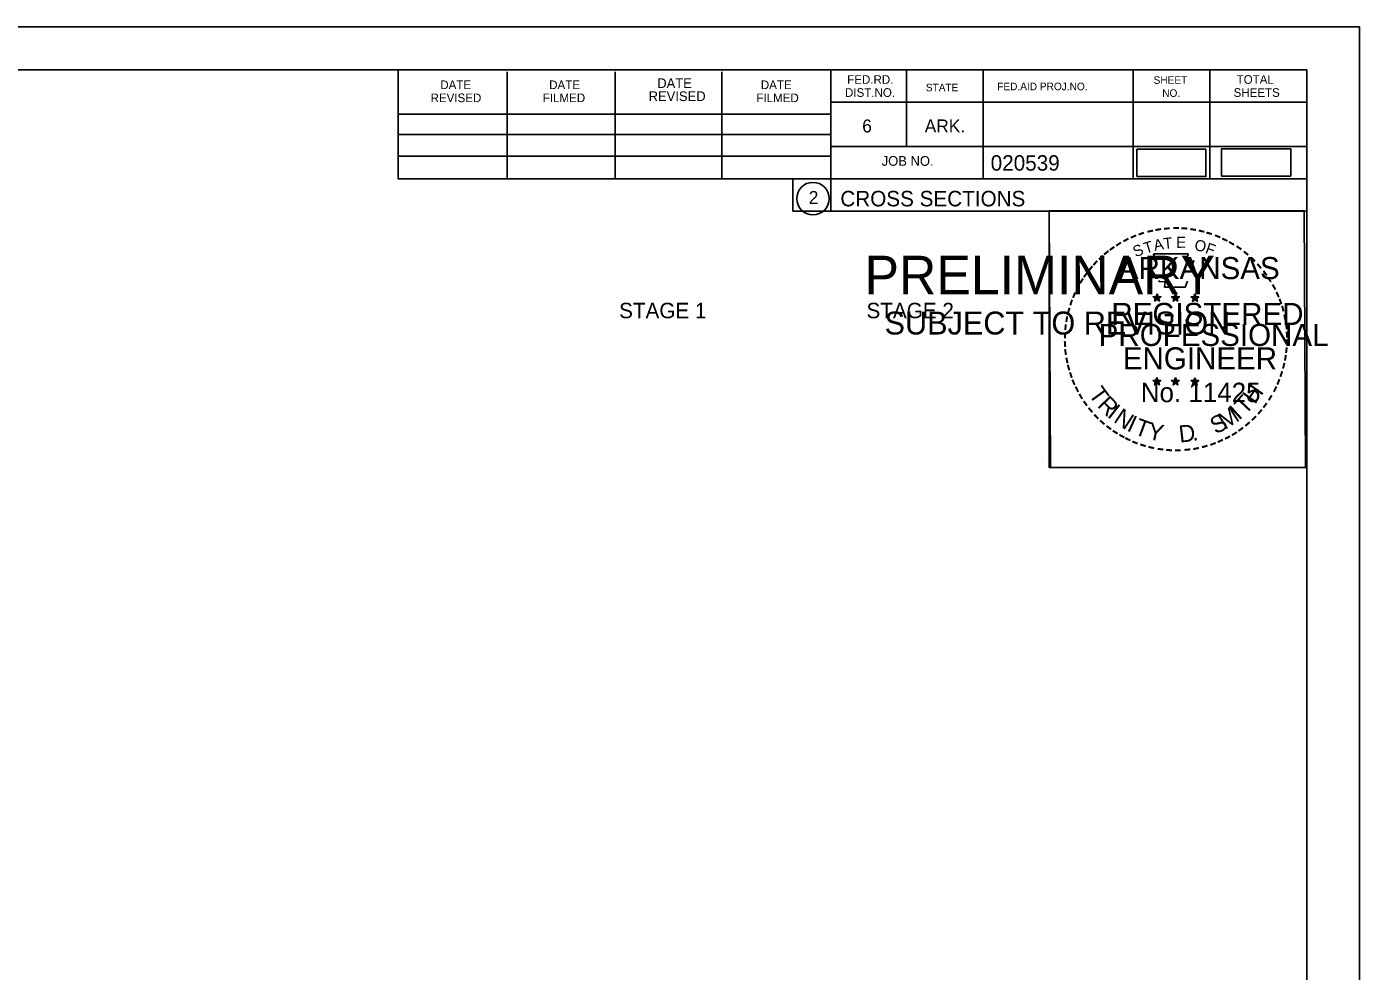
# Model space of a CAD drawing. Extents: x 915787 to 919910, y 133456 to 136717.
# Drawn here: x 916456.2 to 916576.9, y 134223.9 to 134309.4 of the extents above; entities that cross this region are included whole.
import ezdxf

# ---------------------------------------------------------------- set-up
doc = ezdxf.new("R2010")
doc.units = 0
for name, color, linetype in [('R_Border', 7, 'Continuous'), ('R_Border Notes', 7, 'Continuous'), ('R_Border PE', 7, 'Continuous'), ('R_Border Prem', 7, 'Continuous'), ('R_No Plot', 7, 'Continuous'), ('R_Xsect Slope', 7, 'Continuous')]:
    doc.layers.add(name, color=color, linetype=linetype)

msp = doc.modelspace()

# ---------------------------------------------------------------- linework, layer by layer
at = {"layer": 'R_Border'}
for p, q in [((916255.98, 134305.49), (916572.16, 134305.49)), ((916489.9, 134295.61), (916489.9, 134305.49)), ((916499.76, 134295.61), (916499.76, 134305.29)), ((916509.52, 134295.61), (916509.52, 134305.29)), ((916519.2, 134295.61), (916519.2, 134305.29)), ((916529.06, 134305.49), (916529.06, 134292.69)), ((916535.9, 134305.49), (916535.9, 134298.55)), ((916542.84, 134305.49), (916542.84, 134295.61)), ((916556.42, 134305.49), (916556.42, 134295.61)), ((916563.36, 134305.49), (916563.36, 134295.61)), ((916572.16, 134100.03), (916572.16, 134305.49)), ((916572.16, 134302.55), (916529.06, 134302.55)), ((916572.16, 134302.57), (916572.16, 134302.57)), ((916489.9, 134301.47), (916529.06, 134301.47)), ((916489.9, 134299.61), (916529.06, 134299.61)), ((916489.9, 134295.61), (916489.9, 134297.67)), ((916489.9, 134297.67), (916529.06, 134297.67)), ((916572.16, 134298.55), (916529.06, 134298.55)), ((916532.02, 134298.55), (916572.16, 134298.55)), ((916572.16, 134295.61), (916489.9, 134295.61)), ((916529.06, 134292.69), (916572.16, 134292.69))]:
    msp.add_line(p, q, dxfattribs=at)
msp.add_circle((916527.44, 134293.82), 1.47, dxfattribs=at)
at = {"layer": 'R_Border PE'}
for p, q in [((916558.24, 134284.94), (916558.59, 134284.83)), ((916558.24, 134284.94), (916558.49, 134284.9)), ((916558.24, 134284.94), (916558.48, 134284.82)), ((916558.37, 134284.54), (916558.59, 134284.83)), ((916558.37, 134284.54), (916558.5, 134284.78)), ((916558.37, 134284.54), (916558.59, 134284.75)), ((916558.59, 134285.2), (916558.55, 134284.95)), ((916558.59, 134284.83), (916558.59, 134285.2)), ((916558.59, 134285.2), (916558.64, 134284.95)), ((916558.94, 134284.94), (916558.59, 134284.83)), ((916558.8, 134284.54), (916558.59, 134284.83)), ((916558.8, 134284.54), (916558.59, 134284.75)), ((916558.94, 134284.94), (916558.65, 134284.89)), ((916558.8, 134284.54), (916558.66, 134284.83)), ((916558.94, 134284.94), (916558.73, 134284.84)), ((916559.91, 134284.94), (916560.26, 134284.83)), ((916559.91, 134284.94), (916560.16, 134284.9)), ((916559.91, 134284.94), (916560.15, 134284.82)), ((916560.04, 134284.54), (916560.26, 134284.83)), ((916560.04, 134284.54), (916560.17, 134284.78)), ((916560.04, 134284.54), (916560.26, 134284.75)), ((916560.26, 134285.2), (916560.22, 134284.95)), ((916560.26, 134284.83), (916560.26, 134285.2)), ((916560.26, 134285.2), (916560.31, 134284.95)), ((916560.61, 134284.94), (916560.26, 134284.83)), ((916560.47, 134284.54), (916560.26, 134284.83)), ((916560.47, 134284.54), (916560.26, 134284.75)), ((916560.61, 134284.94), (916560.32, 134284.89)), ((916560.47, 134284.54), (916560.33, 134284.83)), ((916560.61, 134284.94), (916560.4, 134284.84)), ((916561.67, 134284.93), (916562.02, 134284.82)), ((916561.67, 134284.93), (916561.93, 134284.89)), ((916561.67, 134284.93), (916561.91, 134284.81)), ((916561.81, 134284.52), (916562.02, 134284.82)), ((916561.81, 134284.52), (916561.93, 134284.77)), ((916561.81, 134284.52), (916562.02, 134284.74)), ((916562.02, 134285.19), (916561.98, 134284.93)), ((916562.02, 134284.82), (916562.02, 134285.19)), ((916562.02, 134285.19), (916562.07, 134284.94)), ((916562.37, 134284.93), (916562.02, 134284.82)), ((916562.24, 134284.52), (916562.02, 134284.82)), ((916562.24, 134284.52), (916562.02, 134284.74)), ((916562.37, 134284.93), (916562.08, 134284.88)), ((916562.24, 134284.52), (916562.1, 134284.81)), ((916562.37, 134284.93), (916562.17, 134284.83)), ((916558.24, 134277.37), (916558.58, 134277.26)), ((916558.24, 134277.37), (916558.49, 134277.33)), ((916558.24, 134277.37), (916558.47, 134277.25)), ((916558.37, 134276.96), (916558.58, 134277.26)), ((916558.37, 134276.96), (916558.49, 134277.21)), ((916558.37, 134276.96), (916558.58, 134277.18)), ((916558.58, 134277.62), (916558.54, 134277.37)), ((916558.58, 134277.26), (916558.58, 134277.62)), ((916558.58, 134277.62), (916558.63, 134277.37)), ((916558.93, 134277.37), (916558.58, 134277.26)), ((916558.8, 134276.96), (916558.58, 134277.26)), ((916558.8, 134276.96), (916558.58, 134277.18)), ((916558.93, 134277.37), (916558.65, 134277.32)), ((916558.8, 134276.96), (916558.66, 134277.25)), ((916558.93, 134277.37), (916558.73, 134277.27)), ((916559.9, 134277.37), (916560.25, 134277.26)), ((916559.9, 134277.37), (916560.16, 134277.33)), ((916559.9, 134277.37), (916560.14, 134277.25)), ((916560.04, 134276.96), (916560.25, 134277.26)), ((916560.04, 134276.96), (916560.16, 134277.21)), ((916560.04, 134276.96), (916560.25, 134277.18)), ((916560.25, 134277.62), (916560.21, 134277.37)), ((916560.25, 134277.26), (916560.25, 134277.62)), ((916560.25, 134277.62), (916560.3, 134277.37)), ((916560.6, 134277.37), (916560.25, 134277.26)), ((916560.47, 134276.96), (916560.25, 134277.26)), ((916560.47, 134276.96), (916560.25, 134277.18)), ((916560.6, 134277.37), (916560.31, 134277.32)), ((916560.47, 134276.96), (916560.33, 134277.25)), ((916560.6, 134277.37), (916560.4, 134277.27)), ((916561.67, 134277.36), (916562.02, 134277.25)), ((916561.67, 134277.36), (916561.92, 134277.32)), ((916561.67, 134277.36), (916561.91, 134277.24)), ((916561.8, 134276.95), (916562.02, 134277.25)), ((916561.8, 134276.95), (916561.93, 134277.2)), ((916561.8, 134276.95), (916562.02, 134277.17)), ((916562.02, 134277.61), (916561.98, 134277.36)), ((916562.02, 134277.25), (916562.02, 134277.61)), ((916562.02, 134277.61), (916562.07, 134277.36)), ((916562.37, 134277.36), (916562.02, 134277.25)), ((916562.23, 134276.95), (916562.02, 134277.25)), ((916562.23, 134276.95), (916562.02, 134277.17)), ((916562.37, 134277.36), (916562.08, 134277.31)), ((916562.23, 134276.95), (916562.1, 134277.24)), ((916562.37, 134277.36), (916562.16, 134277.26))]:
    msp.add_line(p, q, dxfattribs=at)
for points in [[(916558.28, 134288.82), (916558.55, 134287.99)], [(916561.79, 134287.9), (916561.93, 134288.18), (916561.25, 134288.16), (916561.4, 134288.82), (916558.28, 134288.82)], [(916558.77, 134286.4), (916558.77, 134286.31), (916559.34, 134286.29), (916559.28, 134285.82), (916561.15, 134285.82), (916561.35, 134286.36)], [(916558.59, 134285.2), (916558.8, 134284.54), (916558.24, 134284.94), (916558.94, 134284.94), (916558.37, 134284.54), (916558.59, 134285.2)], [(916560.26, 134285.2), (916560.47, 134284.54), (916559.91, 134284.94), (916560.61, 134284.94), (916560.04, 134284.54), (916560.26, 134285.2)], [(916562.02, 134285.19), (916562.24, 134284.52), (916561.67, 134284.93), (916562.37, 134284.93), (916561.81, 134284.52), (916562.02, 134285.19)], [(916558.58, 134277.62), (916558.8, 134276.96), (916558.24, 134277.37), (916558.93, 134277.37), (916558.37, 134276.96), (916558.58, 134277.62)], [(916560.25, 134277.62), (916560.47, 134276.96), (916559.9, 134277.37), (916560.6, 134277.37), (916560.04, 134276.96), (916560.25, 134277.62)], [(916562.02, 134277.61), (916562.23, 134276.95), (916561.67, 134277.36), (916562.37, 134277.36), (916561.8, 134276.95), (916562.02, 134277.61)]]:
    msp.add_lwpolyline(points, dxfattribs=at)
for centre, radius in [((916558.59, 134284.83), 0.172), ((916558.59, 134284.83), 0.145), ((916558.59, 134284.83), 0.116), ((916558.59, 134284.83), 0.0991), ((916558.59, 134284.83), 0.0747), ((916558.59, 134284.83), 0.0495), ((916558.59, 134284.83), 0.0296), ((916560.26, 134284.83), 0.172), ((916560.26, 134284.83), 0.145), ((916560.26, 134284.83), 0.116), ((916560.26, 134284.83), 0.0991), ((916560.26, 134284.83), 0.0747), ((916560.26, 134284.83), 0.0495), ((916560.26, 134284.83), 0.0296), ((916562.02, 134284.82), 0.172), ((916562.02, 134284.82), 0.145), ((916562.02, 134284.82), 0.116), ((916562.02, 134284.82), 0.0991), ((916562.02, 134284.82), 0.0747), ((916562.02, 134284.82), 0.0495), ((916562.02, 134284.82), 0.0296), ((916558.58, 134277.26), 0.172), ((916558.58, 134277.26), 0.145), ((916558.58, 134277.26), 0.116), ((916558.58, 134277.26), 0.0991), ((916558.58, 134277.26), 0.0747), ((916558.58, 134277.26), 0.0495), ((916558.58, 134277.26), 0.0296), ((916560.25, 134277.26), 0.172), ((916560.25, 134277.26), 0.145), ((916560.25, 134277.26), 0.116), ((916560.25, 134277.26), 0.0991), ((916560.25, 134277.26), 0.0747), ((916560.25, 134277.26), 0.0495), ((916560.25, 134277.26), 0.0296), ((916562.02, 134277.25), 0.172), ((916562.02, 134277.25), 0.145), ((916562.02, 134277.25), 0.116), ((916562.02, 134277.25), 0.0991), ((916562.02, 134277.25), 0.0747), ((916562.02, 134277.25), 0.0495), ((916562.02, 134277.25), 0.0296)]:
    msp.add_circle(centre, radius, dxfattribs=at)
at = {"layer": 'R_No Plot'}
for p, q in [((916243.57, 134309.38), (916576.91, 134309.38)), ((916548.19, 134270.23), (916548.19, 134270.23))]:
    msp.add_line(p, q, dxfattribs=at)
for points in [[(916243.57, 134309.38), (916576.91, 134309.38), (916576.91, 134096.05), (916243.57, 134096.05)], [(916489.9, 134305.49), (916489.9, 134295.61), (916525.63, 134295.61), (916525.63, 134292.69), (916548.83, 134292.69), (916548.83, 134269.47), (916572.16, 134269.47), (916572.16, 134100.03), (916255.98, 134100.03), (916255.98, 134305.49)], [(916548.83, 134292.72), (916571.92, 134292.72), (916572.04, 134269.47), (916548.94, 134269.47)]]:
    msp.add_lwpolyline(points, close=True, dxfattribs=at)
at = {"layer": 'R_Xsect Slope'}
for points in [[(916556.77, 134295.81), (916563.02, 134295.81), (916563.02, 134298.29), (916556.77, 134298.29)], [(916564.44, 134295.86), (916570.69, 134295.86), (916570.69, 134298.34), (916564.44, 134298.34)]]:
    msp.add_lwpolyline(points, close=True, dxfattribs=at)

# ---------------------------------------------------------------- texts
at = {"layer": 'R_Border'}
for s, height, p in [('FED.RD.', 0.782, (916530.54, 134304.21)), ('SHEET', 0.684, (916558.28, 134304.21)), ('TOTAL', 0.782, (916565.8, 134304.21)), ('DATE', 0.782, (916493.7, 134303.73)), ('DATE', 0.782, (916503.56, 134303.73)), ('DATE', 0.879, (916513.34, 134303.83)), ('DATE', 0.782, (916522.72, 134303.73)), ('DIST.NO.', 0.782, (916530.34, 134303.03)), ('STATE', 0.684, (916537.66, 134303.53)), ('FED.AID PROJ.NO.', 0.684, (916544.12, 134303.63)), ('NO.', 0.684, (916559.06, 134303.03)), ('SHEETS', 0.782, (916565.52, 134303.03)), ('REVISED', 0.782, (916492.82, 134302.55)), ('FILMED', 0.782, (916502.98, 134302.55)), ('REVISED', 0.879, (916512.56, 134302.65)), ('FILMED', 0.782, (916522.32, 134302.55)), ('6', 1.17, (916531.9, 134299.81)), ('ARK.', 1.172, (916537.56, 134299.81)), ('JOB NO.', 0.879, (916533.66, 134296.79)), ('020539', 1.4, (916543.53, 134296.35)), ('2', 1.17, (916527.06, 134293.34)), ('CROSS SECTIONS', 1.4, (916529.92, 134293.12))]:
    msp.add_text(s, height=height, rotation=360, dxfattribs=at).set_placement(p)
at = {"layer": 'R_Border Notes'}
for s, p in [('STAGE 1', (916509.89, 134282.99)), ('STAGE 2', (916532.29, 134282.99))]:
    msp.add_text(s, height=1.4, dxfattribs=at).set_placement(p)
at = {"layer": 'R_Border PE'}
for s, height, rotation, p in [('-', 1.6, 24.3072, (916556.39, 134289.68)), ('-', 1.6, 19.1761, (916557.03, 134289.95)), ('-', 1.6, 13.6301, (916557.78, 134290.19)), ('-', 1.6, 10.2193, (916558.46, 134290.35)), ('-', 1.6, 5.8968, (916559.19, 134290.46)), ('-', 1.6, 0.1862, (916559.96, 134290.53)), ('-', 1.6, 357.743, (916560.68, 134290.52)), ('-', 1.6, 352.1617, (916561.42, 134290.46)), ('-', 1.6, 347.2049, (916562.14, 134290.35)), ('-', 1.6, 342.3362, (916562.78, 134290.2)), ('-', 1.6, 337.8551, (916563.51, 134289.97)), ('-', 1.6, 36.2317, (916554.59, 134288.6)), ('-', 1.6, 34.0636, (916555.16, 134288.99)), ('-', 1.6, 28.7918, (916555.76, 134289.36)), ('S', 1, 21.594, (916556.64, 134288.5)), ('T', 1, 16.4036, (916557.55, 134288.83)), ('A', 1, 11.2132, (916558.38, 134289.08)), ('T', 1, 6.0228, (916559.22, 134289.25)), ('E', 1, 0.8323, (916560.33, 134289.36)), ('O', 1, 350.4515, (916561.93, 134289.15)), ('F', 1, 340.0707, (916562.89, 134288.92)), ('-', 1.6, 334.1211, (916564.14, 134289.7)), ('-', 1.6, 329.6409, (916564.72, 134289.42)), ('-', 1.6, 325.8627, (916565.37, 134289.06)), ('-', 1.6, 48.423, (916553.23, 134287.32)), ('-', 1.6, 42.9622, (916553.68, 134287.8)), ('-', 1.6, 38.9507, (916554.11, 134288.22)), ('ARKANSAS', 2, 360, (916555.13, 134286.53)), ('-', 1.6, 320.5297, (916565.98, 134288.63)), ('-', 1.6, 315.5786, (916566.58, 134288.14)), ('-', 1.6, 54.2325, (916552.41, 134286.27)), ('-', 1.6, 50.6142, (916552.83, 134286.84)), ('-', 1.6, 309.8797, (916567.14, 134287.59)), ('-', 1.6, 306.6522, (916567.67, 134286.99)), ('-', 1.6, 62.8713, (916551.78, 134285.13)), ('-', 1.6, 58.0706, (916552.09, 134285.74)), ('-', 1.4, 303.6753, (916568.16, 134286.42)), ('-', 1.6, 299.6684, (916568.47, 134285.82)), ('-', 1.6, 72.3945, (916551.3, 134283.89)), ('-', 1.6, 67.7743, (916551.52, 134284.52)), ('REGISTERED', 2, 360, (916554.46, 134282.38)), ('DWB', 0.01, 360, (916558.58, 134284.83)), ('DWB', 0.01, 360, (916560.25, 134284.83)), ('DWB', 0.01, 360, (916562.01, 134284.82)), ('-', 1.6, 294.6628, (916568.8, 134285.2)), ('-', 1.6, 290.5728, (916569.06, 134284.63)), ('-', 1.6, 81.2013, (916550.97, 134282.46)), ('-', 1.6, 75.461, (916551.1, 134283.18)), ('-', 1.6, 285.1233, (916569.29, 134284.05)), ('-', 1.6, 280.5493, (916569.49, 134283.31)), ('-', 1.6, 85.1863, (916550.89, 134281.77)), ('PROFESSIONAL', 2, 360, (916553.31, 134280.48)), ('-', 1.6, 276.5962, (916569.65, 134282.54)), ('-', 1.6, 94.1959, (916550.9, 134280.35)), ('-', 1.6, 89.0622, (916550.87, 134281.07)), ('-', 1.6, 274.3301, (916569.71, 134281.82)), ('-', 1.6, 269.9407, (916569.75, 134281.18)), ('-', 1.6, 98.9479, (916550.97, 134279.68)), ('ENGINEER', 2, 360, (916555.49, 134278.36)), ('-', 1.6, 260.9953, (916569.66, 134279.86)), ('-', 1.6, 263.5172, (916569.73, 134280.52)), ('-', 1.6, 101.7149, (916551.11, 134278.95)), ('-', 1.6, 105.4578, (916551.27, 134278.35)), ('-', 1.6, 255.7626, (916569.55, 134279.19)), ('-', 1.6, 109.0874, (916551.49, 134277.72)), ('-', 1.6, 114.0643, (916551.74, 134277.12)), ('No. 11425', 1.757, 360, (916557.12, 134275.4)), ('DWB', 0.01, 360, (916558.57, 134277.25)), ('DWB', 0.01, 360, (916560.24, 134277.26)), ('DWB', 0.01, 360, (916562.01, 134277.25)), ('-', 1.6, 247.8887, (916569.14, 134277.79)), ('-', 1.6, 252.8681, (916569.36, 134278.47)), ('-', 1.6, 115.7289, (916552.05, 134276.51)), ('-', 1.6, 120.4471, (916552.4, 134275.92)), ('T', 1.54, 306.0406, (916552.34, 134276.1)), ('R', 1.54, 314.005, (916553.11, 134275.05)), ('T', 1.54, 46.6444, (916566.58, 134274.19)), ('H', 1.54, 54.6088, (916567.46, 134275.13)), ('-', 1.6, 239.0712, (916568.49, 134276.41)), ('-', 1.6, 244.6197, (916568.88, 134277.16)), ('-', 1.6, 125.8934, (916552.81, 134275.36)), ('-', 1.6, 130.7181, (916553.27, 134274.81)), ('I', 1.54, 321.9694, (916554.01, 134274.12)), ('N', 1.54, 326.5002, (916554.57, 134273.65)), ('M', 1.54, 32.6563, (916564.73, 134272.87)), ('I', 1.54, 42.1136, (916566.01, 134273.71)), ('-', 1.6, 231.2538, (916567.65, 134275.19)), ('-', 1.6, 233.8452, (916568.08, 134275.76)), ('-', 1.6, 134.2238, (916553.78, 134274.26)), ('-', 1.6, 138.9338, (916554.31, 134273.8)), ('I', 1.54, 335.3603, (916555.78, 134272.86)), ('T', 1.54, 339.8912, (916556.44, 134272.53)), ('Y', 1.54, 347.8556, (916557.66, 134272.09)), ('S', 1.54, 26.9312, (916563.89, 134272.46)), ('-', 1.6, 221.0851, (916566.65, 134274.12)), ('-', 1.6, 225.7653, (916567.17, 134274.63)), ('-', 1.6, 144.6463, (916554.87, 134273.39)), ('-', 1.6, 148.0898, (916555.43, 134273.02)), ('-', 1.6, 151.5704, (916556.01, 134272.7)), ('D', 1.54, 6.3969, (916560.65, 134271.73)), ('-', 1.6, 207.3568, (916565.01, 134272.91)), ('-', 1.6, 212.2491, (916565.57, 134273.26)), ('-', 1.6, 215.7363, (916566.1, 134273.65)), ('-', 1.6, 154.6002, (916556.53, 134272.45)), ('-', 1.6, 158.5612, (916557.15, 134272.19)), ('-', 1.6, 162.7983, (916557.84, 134271.98)), ('-', 1.6, 167.5555, (916558.55, 134271.82)), ('-', 1.6, 173.1155, (916559.33, 134271.71)), ('-', 1.6, 176.5183, (916560.07, 134271.65)), ('-', 1.6, 181.5918, (916560.82, 134271.67)), ('-', 1.6, 185.8167, (916561.63, 134271.75)), ('-', 1.6, 191.2858, (916562.36, 134271.88)), ('.', 1.54, 13.7642, (916561.84, 134271.86)), ('-', 1.6, 195.4743, (916563.09, 134272.08)), ('-', 1.6, 200.7184, (916563.77, 134272.32)), ('-', 1.6, 204.2516, (916564.39, 134272.6))]:
    msp.add_text(s, height=height, rotation=rotation, dxfattribs=at).set_placement(p)
at = {"layer": 'R_Border Prem'}
for s, height, p in [('PRELIMINARY', 3.5, (916532.11, 134285.15)), ('DWB', 0.01, (916532.85, 134287)), ('SUBJECT TO REVISION', 2.0751, (916533.92, 134281.52))]:
    msp.add_text(s, height=height, rotation=360, dxfattribs=at).set_placement(p)

doc.saveas('drawing.dxf')
